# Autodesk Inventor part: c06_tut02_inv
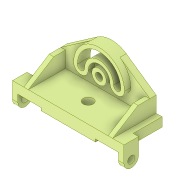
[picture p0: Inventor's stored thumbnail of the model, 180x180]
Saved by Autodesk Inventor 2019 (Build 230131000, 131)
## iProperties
Created: 2015-03
Part Number: c06_tut02_inv
Material: Generic
Document SubType Name: Modeling
Designer: Sandeep
Density: 1 g/cm^3
Appearance: Zinc Chromate 2
Author: Sandeep
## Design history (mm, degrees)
sketch "Sketch1"
  geometry: L1 (0, 0)-(-51, 0); L2 (-51, 0)-(-51, -6); L3 (-51, -6)-(-171, -6); L4 (-171, -6)-(-171, 0); L5 (-171, 0)-(-222, 0); L6 (-222, 0)-(-222, 20); L7 (-222, 20)-(0, 20); L8 (0, 20)-(0, 0)
  constraints: 16 end point, 6 perpendicular, 2 point on line, 1 horizontal
  dimensions: "d0" = 20 distance of L5.end L6.end; "d1" = 26 distance between parallel lines of L3 L7; "d2" = 120 distance of L4.end L1.end; "d3" = 51 distance between parallel lines of L2 L8; "d4" = 51 distance from line of L4.end L6
extrude "Extrusion1" new body sketch "Sketch1" distance "d5" = 96; taper "d6" = 0 deg
sketch "Sketch2"
  geometry: L1 (209, -20)-(209, -55); L2 (209, -55)-(143, -100.957); L3 (79, -100.957)-(13, -55); L4 (13, -55)-(13, -20); L5 (222, -20)-(0, -20) reference; L6 (13, -20)-(209, -20); L7 (222, -20)-(222, 0) reference; L8 (209, -55)-(-58.567, -55); A1 r 56 centre (111, -55) between (79, -100.957) and (143, -100.957); 1 further point
  constraints: 12 end point, 2 parallel, 2 point on circle, 2 point on line, 2 tangent, 1 centre point, 1 collinear, 1 horizontal, 1 vertical
  dimensions: "d7" = 13 distance from line of point (0, 0) L4; "d8" = 13 distance between parallel lines of L1 L7; "d10" = 56 radius of A1; "d11" = 98 distance from line of L1 A1.centre; "d13" = 35 distance of L1.start L1.end
extrude "Extrusion2" join sketch "Sketch2" distance "d14" = 14; taper "d15" = 0 deg
sketch "Sketch4"
  geometry: L1 (111, 55)-(-9.927, 55); C1 r 16 at (111, 55); A1 r 40 centre (111, 55) between (151, 55) and (71, 55); A2 r 56 centre (111, 55) between (167, 55) and (55, 55); A3 r 24 centre (111, 55) between (135, 55) and (87, 55); A4 r 16 centre (151, 55) between (135, 55) and (167, 55); A5 r 16 centre (71, 55) between (55, 55) and (87, 55); A6 r 56 centre (111, 55) between (143, 100.957) and (79, 100.957) reference
  constraints: 10 point on circle, 6 centre point, 4 tangent, 2 end point, 2 point on line, 1 coincident, 1 concentric, 1 horizontal
  dimensions: "d20" = 56 radius of A2; "d21" = 24 radius of A3; "d22" = 32 diameter of C1
extrude "Extrusion3" join sketch "Sketch4" distance "d23" = 14; taper "d24" = 0 deg
sketch "Sketch7"
  geometry: C1 r 8 at (111, 55); A1 r 16 centre (151, 55) between (135, 55) and (167, 55) reference; A2 r 16 centre (71, 55) between (55, 55) and (87, 55) reference; A3 r 40 centre (111, 55) between (151, 55) and (71, 55); A4 r 48 centre (111, 55) between (159, 55) and (63, 55); A5 r 32 centre (111, 55) between (143, 55) and (79, 55); A6 r 8 centre (151, 55) between (143, 55) and (159, 55); A7 r 8 centre (71, 55) between (63, 55) and (79, 55); A8 r 56 centre (111, 55) between (167, 55) and (55, 55) reference; 1 further point
  constraints: 10 point on circle, 6 centre point, 4 tangent, 1 coincident, 1 concentric
  dimensions: "d26" = 8 radius of A6; "d27" = 16 diameter of C1
extrude "Extrusion4" cut sketch "Sketch7" extent not by distance; stored distance "d28" = 14; taper "d29" = 0 deg
workplane "Work Plane1"
sketch "Sketch12"
  geometry: L1 (35, -96)-(35, 0) reference; L2 (35, -13.954)-(35, -96); L3 (35, -96)-(0, -40); L4 (0, -40)-(0, -14); L5 (0, 0)-(-45.957, 0) reference; 1 further point
  constraints: 6 end point, 1 collinear, 1 parallel, 1 point on line
  dimensions: "d34" = 35 distance between parallel lines of L1 L4; "d35" = 40 distance from line of L5 L3.end
feature "Rib1" sketch "Sketch12" dims "d36" = 1, "d37" = 10, "d38" = 0, "d39" = 0, "d40" = 1, "d41" = 1
sketch "Sketch14"
  geometry: L1 (0, 0)-(0, 32); L2 (0, 32)-(36, 32); L3 (36, 0)-(0, 0); L4 (0, 96)-(0, 0) reference; C1 r 8 at (36, 16); A1 r 16 centre (36, 16) between (36, 0) and (36, 32); 1 further point
  constraints: 6 end point, 2 centre point, 2 point on circle, 2 tangent, 1 coincident, 1 horizontal, 1 perpendicular, 1 point on line
  dimensions: "d42" = 36 distance from line of L1 A1.centre; "d43" = 16 radius of A1; "d44" = 16 diameter of C1
extrude "Extrusion5" join sketch "Sketch14" distance "d45" = 12; taper "d46" = 0 deg
workplane "Work Plane2"
mirror "Mirror1"
hole "Hole1" diameter "d50" = 22; stored, may be unused: countersink angle "d54" = 90 deg, drill point angle "d56" = 118 deg; dims "d48" = 88, "d49" = 38, "d51" = 6, "d52" = 4, "d53" = 2, "d55" = 8
body "Solid1"
other parameters: "d32" = 0, "d47" = -111
